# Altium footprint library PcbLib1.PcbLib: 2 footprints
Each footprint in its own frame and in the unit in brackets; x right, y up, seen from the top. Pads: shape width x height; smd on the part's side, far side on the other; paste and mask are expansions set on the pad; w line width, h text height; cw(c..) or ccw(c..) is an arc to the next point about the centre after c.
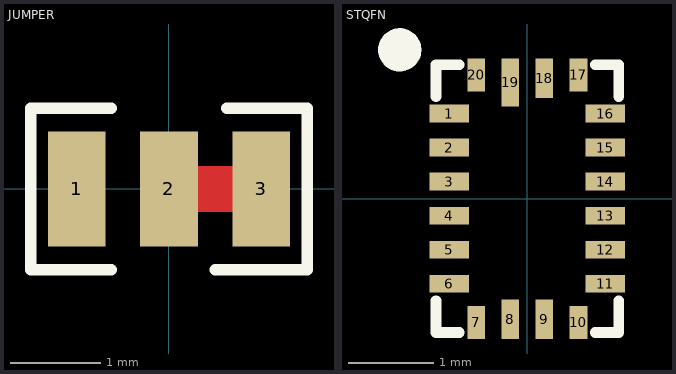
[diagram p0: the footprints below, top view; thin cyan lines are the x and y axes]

## JUMPER [mil]
pads (3):
  rect 25x50 smd: 1(-40,0) 2(0,0) 3(40,0)
Top Layer:
  lines w20: 0,0 40,0
Top Overlay:
  lines w5: -25,-35 -60,-35 -60,35 -25,35 ; 20,-35 60,-35 60,35 25,35

## STQFN [mm] "PACKAGE OUTLINES FOR STQFN 20L 2 MM X 3 MM 0.4P FCD"
height 0.55
pads (20):
  rect 0.465x0.21 smd: 1(-0.917,1) 2(-0.917,0.6) 3(-0.917,0.2) 4(-0.917,-0.2) 5(-0.917,-0.6) 6(-0.917,-1) 11(0.917,-1) 12(0.917,-0.6) 13(0.917,-0.2) 14(0.917,0.2) 15(0.917,0.6) 16(0.917,1)
  rect 0.21x0.39 smd: 7(-0.6,-1.455) 10(0.6,-1.455) 17(0.6,1.455) 20(-0.6,1.455)
  rect 0.21x0.465 smd: 8(-0.2,-1.418) 9(0.2,-1.418) 18(0.2,1.418)
  rect 0.21x0.565 smd: 19(-0.2,1.368)
Top Overlay:
  circle w0.254: c-1.5,1.75 r0.127
  lines w0.127: -1.075,-1.2 -1.075,-1.575 -0.8,-1.575 ; -1.075,1.2 -1.075,1.575 -0.8,1.575 ; 0.8,-1.575 1.075,-1.575 1.075,-1.2 ; 0.8,1.575 1.075,1.575 1.075,1.2
3D body: height 0.55, standoff 0, extent -1,-1.5 1,1.5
